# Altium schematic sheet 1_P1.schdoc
size 307 x 218 mm; Symbol: Drawing-Symbol_A4; Device: Drawing-Symbol_A4; Company: 嘉立创EDA; Version: V1.0; Page Size: A4; @Project Name: backscatter; @Page Count: 1; @Update Date: 2026-05-21; @Create Date: 2026-05-20; @Schematic Name: Schematic2; @Page No: 1; @Page Name: P1; @Board Name: Board2; @Create Time: 12:05:58; @Update Time: 22:00:18; Title Block Position: 3; Size: A4; Width: 1170; Height: 825; Region Start: 1; X Region Count: 6; Y Region Count: 4; Blade Width: 10
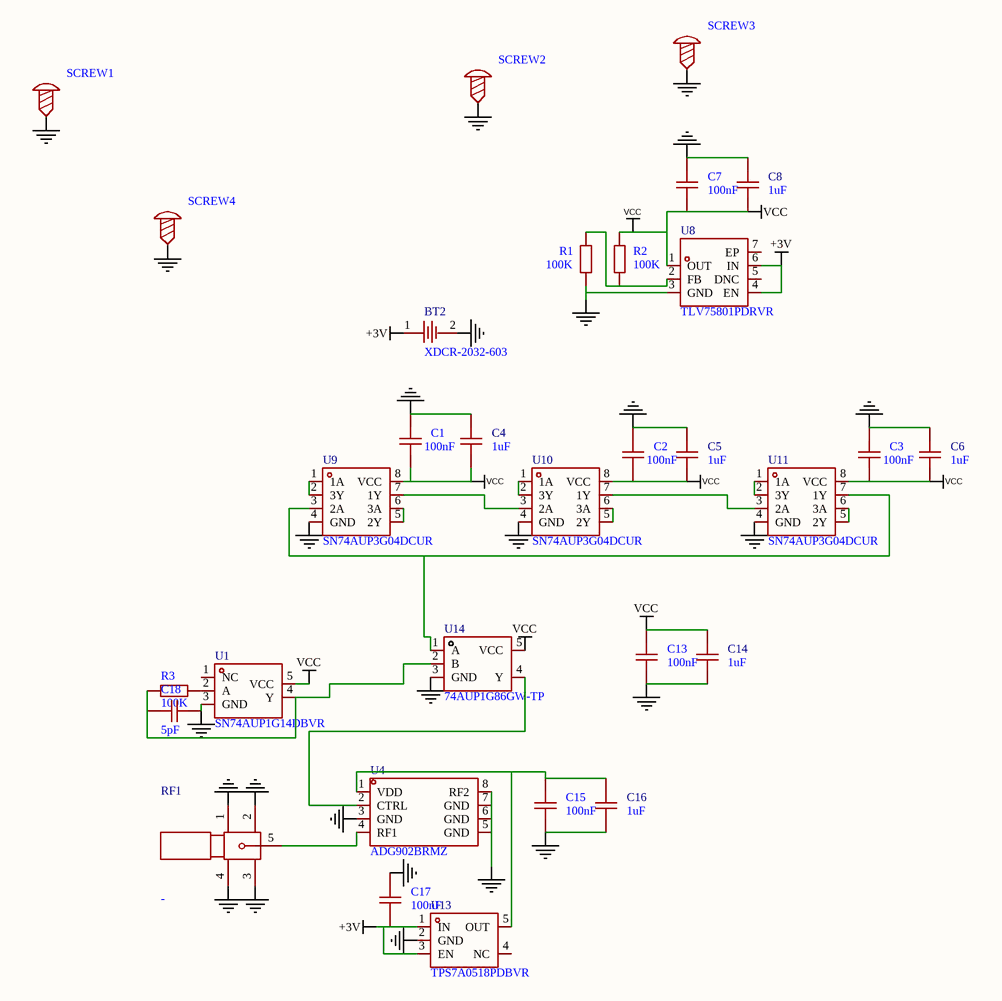
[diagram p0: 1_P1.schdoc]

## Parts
BT2  XDCR-2032-603  [BAT-SMD_XDCR-2032-603]
C1  100nF  [C0603]
C2  100nF  [C0603]
C3  100nF  [C0603]
C4  1uF  [C0603]
C5  1uF  [C0603]
C6  1uF  [C0603]
C7  100nF  [C0603]
C8  1uF  [C0603]
C13  100nF  [C0603]
C14  1uF  [C0603]
C15  100nF  [C0603]
C16  1uF  [C0603]
C17  100nF  [C0603]
C18  5pF  [C0603]
R1  100K  [R0603]
R2  100K  [R0603]
R3  100K  [R0603]
RF1  -  [SMA-SMD_BWSMA-KE-P001]
SCREW1  (no value)  [M3螺丝]
SCREW2  (no value)  [M3螺丝]
SCREW3  (no value)  [M3螺丝]
SCREW4  (no value)  [M3螺丝]
U1  SN74AUP1G14DBVR  [SOT-23-5_L2.9-W1.6-P0.95-LS2.8-BR]
U4  ADG902BRMZ  [MSOP-8_L3.0-W3.0-P0.65-LS5.0-BL]
U8  TLV75801PDRVR  [WSON-6_L2.0-W2.0-P0.65-TL-EP]
U9  SN74AUP3G04DCUR  [VSSOP-8_L2.3-W2.0-P0.50-LS3.1-BL]
U10  SN74AUP3G04DCUR  [VSSOP-8_L2.3-W2.0-P0.50-LS3.1-BL]
U11  SN74AUP3G04DCUR  [VSSOP-8_L2.3-W2.0-P0.50-LS3.1-BL]
U13  TPS7A0518PDBVR  [SOT-23-5_L3.0-W1.7-P0.95-LS2.8-BR]
U14  74AUP1G86GW-TP  [SOT-353_L2.1-W1.3-P0.65-LS2.3-BR]

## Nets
+3V: BT2.1 C17.2 U8.4(EN) U8.6(IN) U13.1(IN) U13.3(EN)
GND: BT2.2 C1.2 C2.2 C3.2 C4.2 C5.2 C6.2 C7.2 C8.2 C13.1 C14.1 C15.1 C16.1 C17.1 C18.1 R1.1 RF1.1 RF1.2 RF1.3 RF1.4 SCREW1.1 SCREW2.1 SCREW3.1 SCREW4.1 U1.3(GND) U4.3(GND) U4.5(GND) U4.6(GND) U4.7(GND) U4.8(RF2) U8.3(GND) U9.4(GND) U10.4(GND) U11.4(GND) U13.2(GND) U14.3(GND)
VCC: C1.1 C2.1 C3.1 C4.1 C5.1 C6.1 C7.1 C8.1 C13.2 C14.2 R2.2 U1.5(VCC) U8.1(OUT) U9.8(VCC) U10.8(VCC) U11.8(VCC) U14.5(VCC)
NetC15_2: C15.2 C16.2 U4.1(VDD) U13.5(OUT)
NetC18_2: C18.2 R3.2 U1.4(Y) U14.2(B)
NetR1_2: R1.2 R2.1 U8.2(FB)
NetR3_1: R3.1 U1.2(A)
NetRF1_5: RF1.5 U4.4(RF1)
NetU4_2: U4.2(CTRL) U14.4(Y)
NetU9_1: U9.1(1A) U9.2(3Y)
NetU9_3: U9.3(2A) U11.7(1Y) U14.1(A)
NetU9_5: U9.5(2Y) U9.6(3A)
NetU9_7: U9.7(1Y) U10.3(2A)
NetU10_1: U10.1(1A) U10.2(3Y)
NetU10_5: U10.5(2Y) U10.6(3A)
NetU10_7: U10.7(1Y) U11.3(2A)
NetU11_1: U11.1(1A) U11.2(3Y)
NetU11_5: U11.5(2Y) U11.6(3A)

Not connected (* = marked no-connect by the designer): U1 1(NC); U8 5(DNC) 7(EP); U13 4(NC)

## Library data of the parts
BT2 = XDCR-2032-603: Manufacturer: LX(连欣科技); Add into BOM: yes; Connector Type: 电池底座; Battery Type: CR2032
C1-C3 C7 C13 C15 C17 C18 = CAP_0603: Symbol: CapAcitance; Convert to PCB: yes
C4-C6 C8 C14 C16 = CGA0603X5R105K500JT: Manufacturer: HRE(芯声); Add into BOM: yes; Tolerance: ±10%; Voltage Rating: 50V; Temperature Coefficient: X5R
R1-R3 = Res_0603: Symbol: 电阻; Convert to PCB: yes
RF1 = BWSMA-KE-P001: Manufacturer: BAT WIRELESS(蝙蝠无线); Add into BOM: yes; Connector Type: 板端; Interface: 内孔; Number of Ports: 1; Interface Diameter: 5.2mm; RF Series: SMA; Impedance: 50Ω; Style: 偏脚
SCREW1-SCREW4 = M3螺丝: Symbol: 螺丝孔; Convert to PCB: yes
U1 = SN74AUP1G14DBVR: Manufacturer: TI(德州仪器); Add into BOM: yes; Input Type: 施密特触发器; Voltage - Supply: 800mV~3.6V; Current - Supply: 500nA; Number of Circuits: 1; Current - Output Low(IOL): 4mA; Input Logic Level - High: 600mV~2.29V; Input Logic Level -Low: 100mV~880mV; Max Propagation Delay: 6.2ns@3.3V,30pF
U4 = ADG902BRMZ: Manufacturer: ADI(亚德诺); Add into BOM: yes; isolation: 40dB; Insertion loss: 0.8dB; Frequency range: 0Hz~2.5GHz; Supply voltage: 1.65V~2.75V
U8 = TLV75801PDRVR: Manufacturer: TI(德州仪器); Add into BOM: yes; Output Type: 可调; Maximum Input Voltage: 6V; Output Voltage: 550mV~5.5V; Output Current: 500mA; Dropout Voltage: 880mV@(500mA); standby current: 31uA; Output Polarity: 正极; Number of Outputs: 1
U9-U11 = SN74AUP3G04DCUR: Manufacturer: TI(德州仪器); Add into BOM: yes; Voltage - Supply: 800mV~3.6V; Quiescent Current(Iq): 900nA; Number of Circuits: 3; Current - Output Low(IOL): 4mA; Propagation Delay: 3.4ns@3.3V,15pF
U13 = TPS7A0518PDBVR: Manufacturer: TI(德州仪器); Add into BOM: yes; Output Type: 固定; Maximum Input Voltage: 5.5V; Output Voltage: 1.8V; Output Current: 200mA; Dropout Voltage: 382mV@(200mA); standby current: 3uA; Output Polarity: 正极; Number of Outputs: 1
U14 = 74AUP1G86GW-TP: Manufacturer: TECH PUBLIC(台舟); Add into BOM: yes; Logic Type: 异或门; Number of Channels: 1; Voltage - Supply: 800mV~3.6V; Quiescent Current: 500nA; Current - Output Low(IOL): 4mA; Output Logic Level - High: 1.32V；1.9V；2.72V；1.11V；2.05V；2.6V; Output Logic Level - Low: 310mV；440mV; Propagation Delay: 4.4ns@3.3V,30pF; Input Number: 2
